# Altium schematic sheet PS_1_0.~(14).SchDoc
size A4
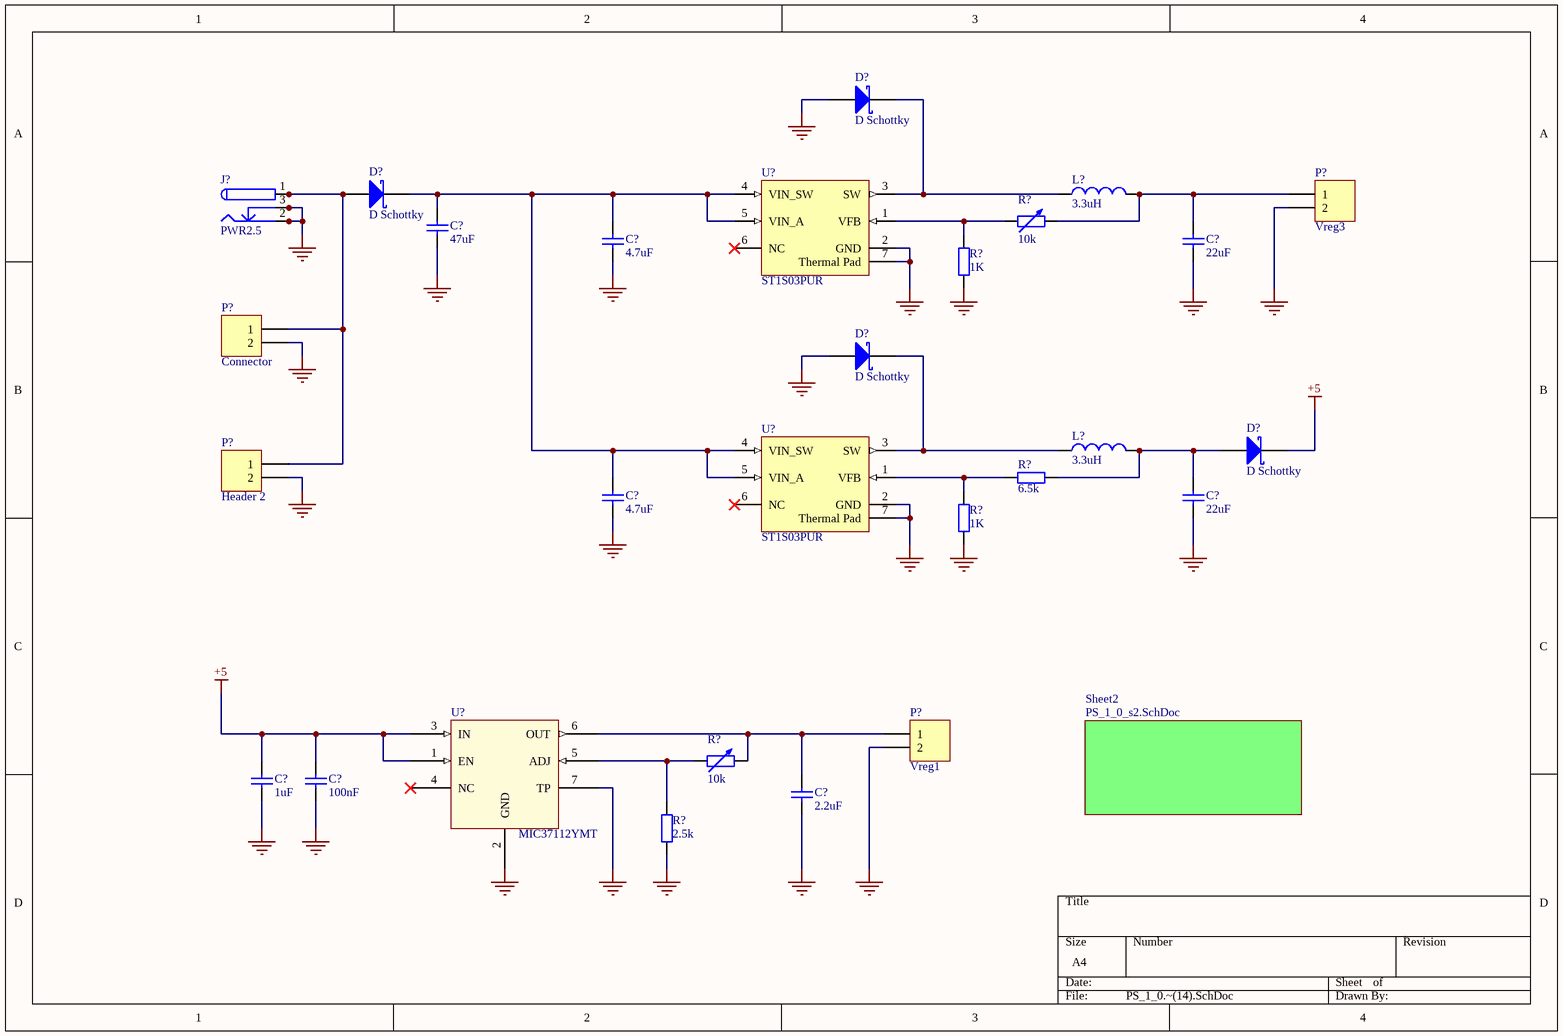
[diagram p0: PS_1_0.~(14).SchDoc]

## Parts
(Parts that share a designator on the sheet are numbered #1, #2 ... from top to bottom, then left to right.)
C?#1  47uF  [C0805]
C?#2  4.7uF  [C0805]
C?#3  22uF  [C0805]
C?#4  4.7uF  [C0805]
C?#5  22uF  [C0805]
C?#6  1uF  [0603]
C?#7  100nF  [0603]
C?#8  2.2uF  [0603]
D?#1  D Schottky  [SMB]
D?#2  D Schottky  [SMB]
D?#3  D Schottky  [SMB]
D?#4  D Schottky  [SMB]
J?  PWR2.5  [KLD-0202]
L?#1  3.3uH  [0402-A]
L?#2  3.3uH  [0402-A]
P?#1  Vreg3  [HDR1X2]
P?#2  Connector  [L_ZAC]
P?#3  Header 2  [HDR1X2]
P?#4  Vreg1  [HDR1X2]
R?#1  10k  [AXIAL-0.6]
R?#2  1K  [0603]
R?#3  6.5k  [0603]
R?#4  1K  [0603]
R?#5  10k  [AXIAL-0.6]
R?#6  2.5k  [0603]
U?#1  ST1S03PUR  [DFN6D_M]
U?#2  ST1S03PUR  [DFN6D_M]
U?#3  MIC37112YMT

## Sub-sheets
Sheet2 = PS_1_0_s2.SchDoc: no entries

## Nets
+5: C?#6.1 C?#7.1 D?#4.2(K) U?#3.1(EN) U?#3.3(IN)
GND: C?#1.2 C?#2.2 C?#3.2 C?#4.2 C?#5.2 C?#6.2 C?#7.2 C?#8.2 D?#1.1(A) D?#3.1(A) J?.2 J?.2A J?.2B J?.3 J?.3A J?.3B P?#1.2 P?#2.2 P?#3.2 P?#4.2 R?#2.1 R?#4.1 R?#6.1 U?#1.2(GND) U?#1.7(Thermal_Pad) U?#2.2(GND) U?#2.7(Thermal_Pad) U?#3.2(GND) U?#3.7(TP)
NetC?#1_1: C?#1.1 C?#2.1 C?#4.1 D?#2.2(K) U?#1.4(VIN_SW) U?#1.5(VIN_A) U?#2.4(VIN_SW) U?#2.5(VIN_A)
NetC?#3_1: C?#3.1 L?#1.2 P?#1.1 R?#1.2
NetC?#5_1: C?#5.1 D?#4.1(A) L?#2.2 R?#3.1
NetC?#8_1: C?#8.1 P?#4.1 R?#5.2 U?#3.6(OUT)
NetD?#1_2: D?#1.2(K) L?#1.1 U?#1.3(SW)
NetD?#2_1: D?#2.1(A) J?.1 J?.1A J?.1B P?#2.1 P?#3.1
NetD?#3_2: D?#3.2(K) L?#2.1 U?#2.3(SW)
NetR?#1_1: R?#1.1 R?#2.2 U?#1.1(VFB)
NetR?#3_2: R?#3.2 R?#4.2 U?#2.1(VFB)
NetR?#5_1: R?#5.1 R?#6.2 U?#3.5(ADJ)

Not connected (* = marked no-connect by the designer): U?#1 6(NC)*; U?#2 6(NC)*; U?#3 4(NC)*

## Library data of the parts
C?#1-C?#8 = Cap Semi: Capacitor (Semiconductor SIM Model)
D?#1-D?#4 = D Schottky: Schottky Diode
J? = PWR2.5: Low Voltage Power Supply Connector
L?#1 L?#2 = Inductor: Code_IEC: 1005
P?#1-P?#4 = Header 2: Header, 2-Pin
R?#1 R?#5 = Res Adj2: Variable Resistor; Set Position: 0.5
R?#2-R?#4 R?#6 = Res2: Resistor
U?#1 U?#2 = ST1S03PUR: 1.5 A, 1.5 MHz adjustable, step-down switching regulator, DFN6D
U?#3 = MIC37112YMT: LDO, 1A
